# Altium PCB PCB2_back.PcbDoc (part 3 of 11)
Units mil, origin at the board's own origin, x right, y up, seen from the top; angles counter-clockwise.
Board outline 6299 x 3937 mil, 4 copper layers (TopLayer, GROUND, VCC, BottomLayer); 290 components, 470 nets, 2252 pads, 825 vias.
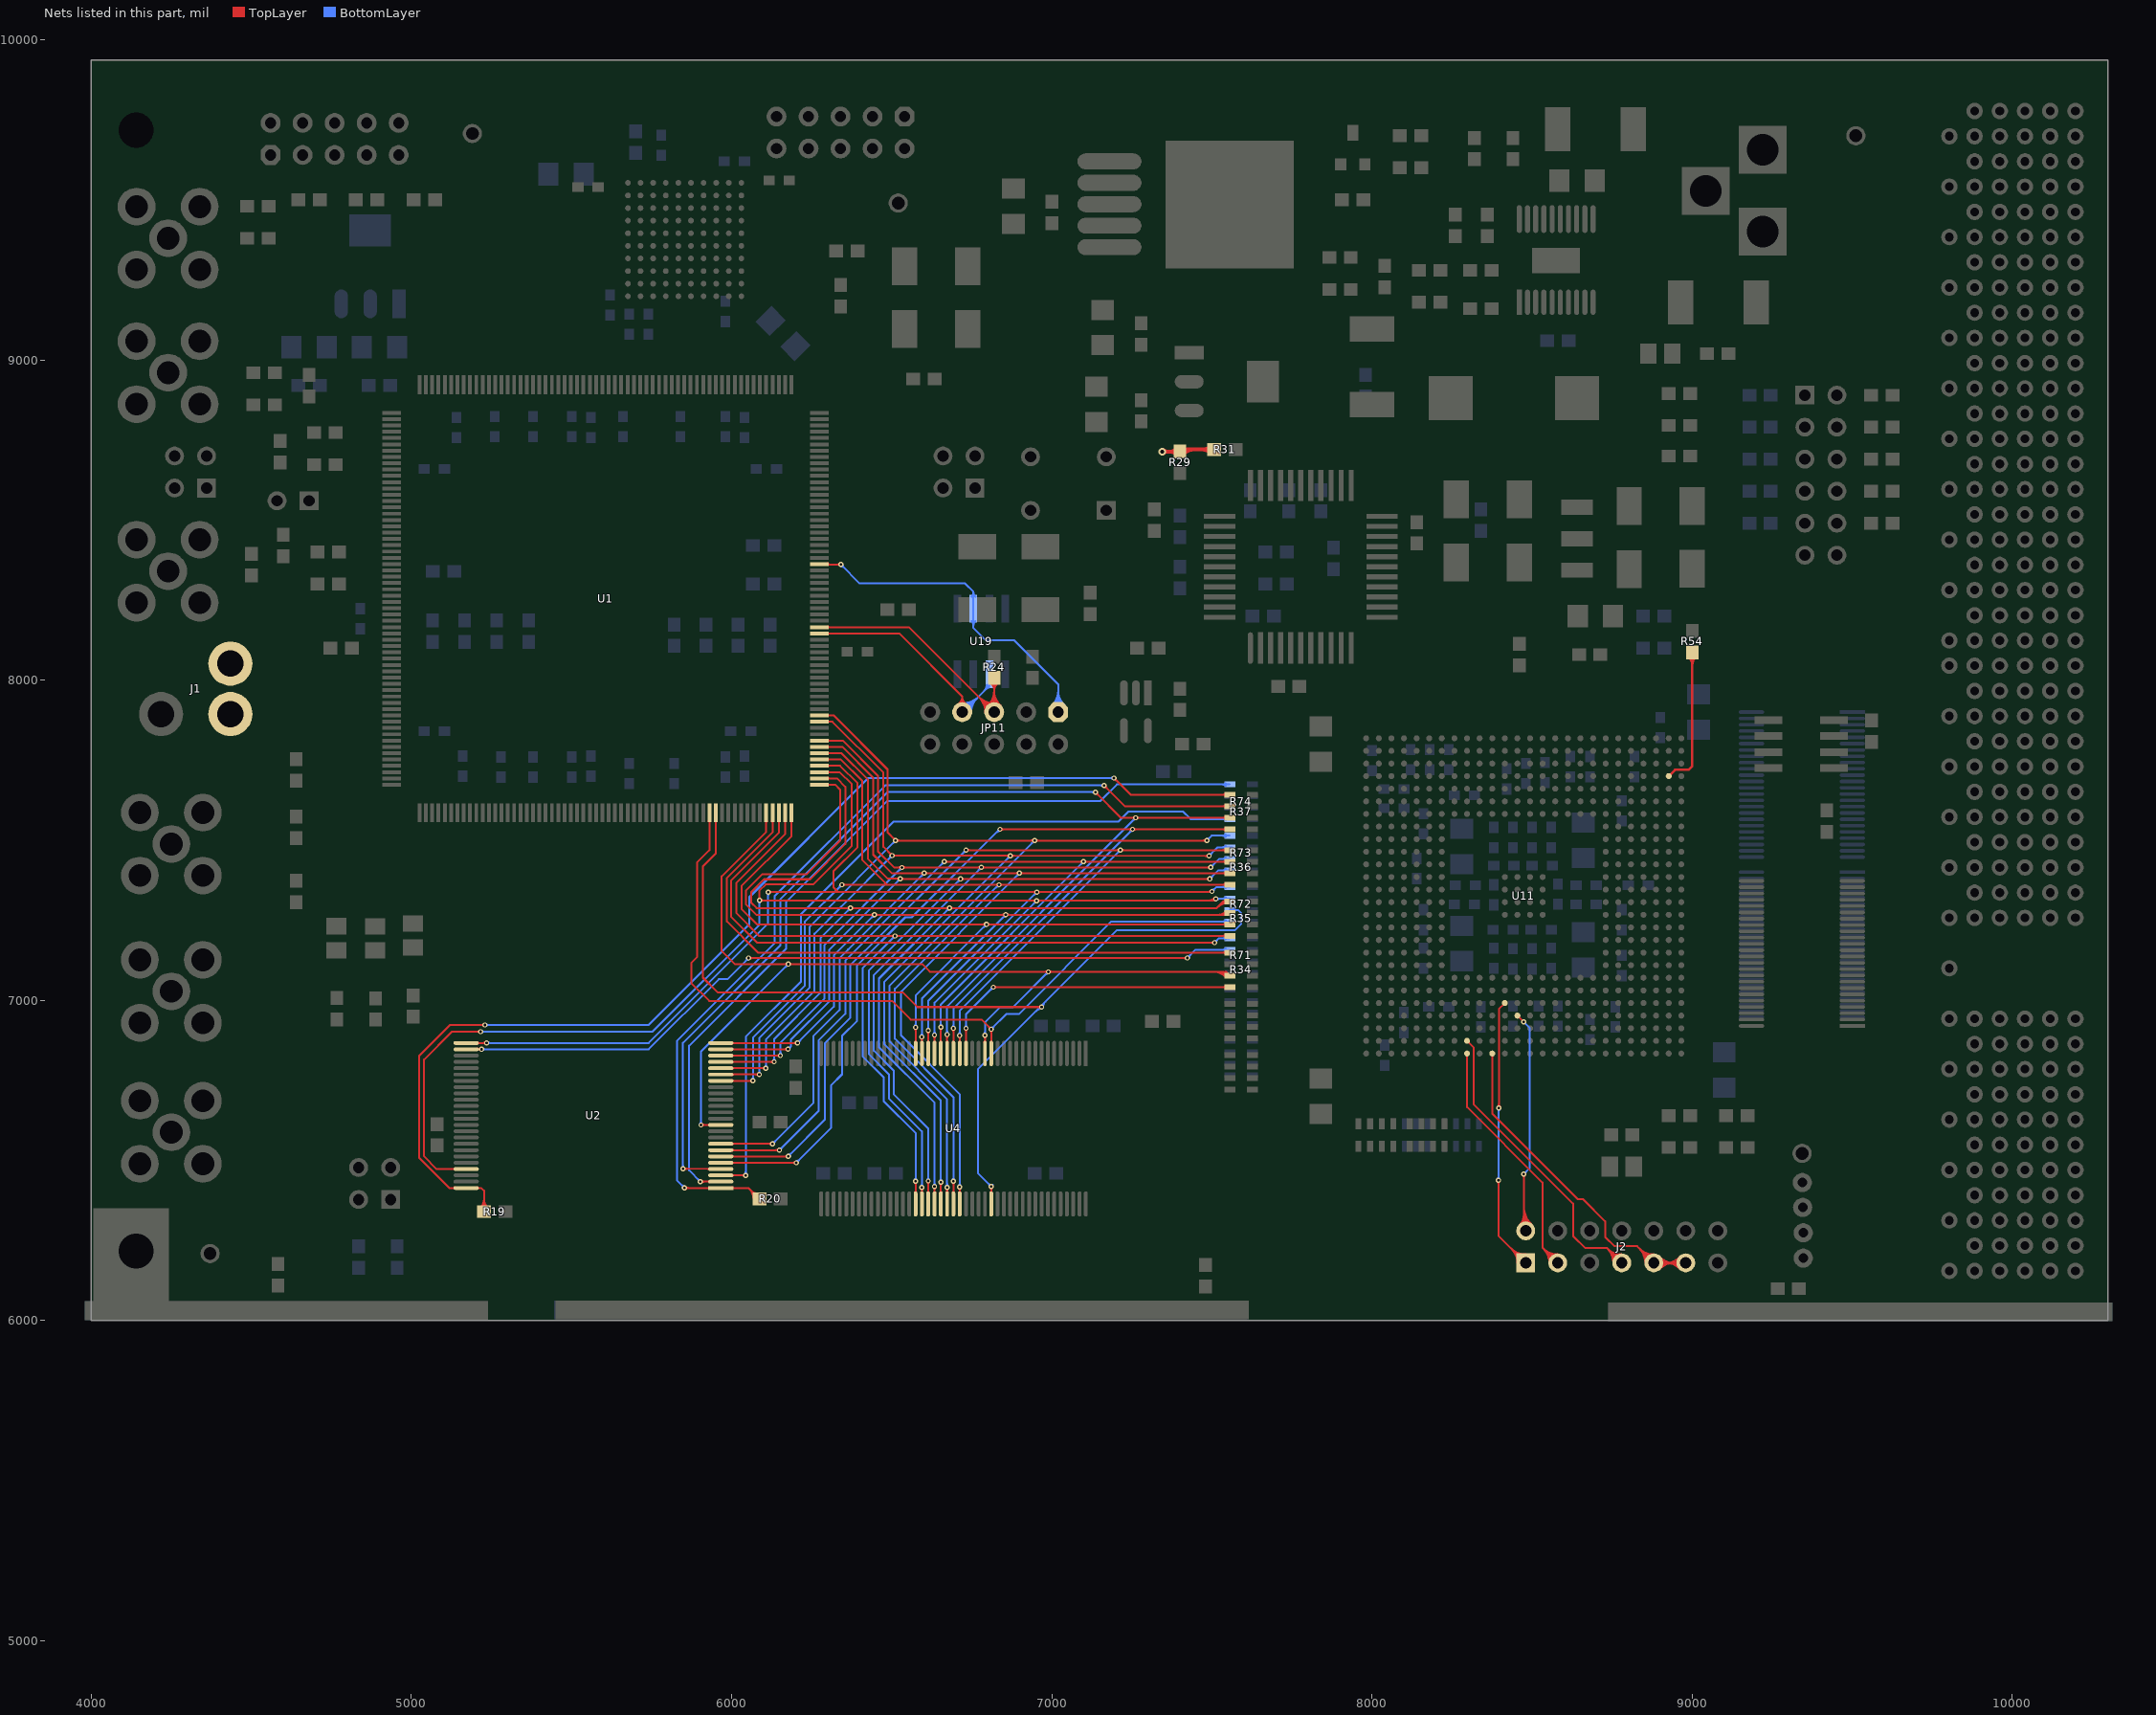
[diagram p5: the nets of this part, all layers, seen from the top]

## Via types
v1: diameter 16, hole 8, TopLayer to BottomLayer, 408 vias
v2: diameter 20, hole 10, TopLayer to BottomLayer, 221 vias
v3: diameter 24, hole 12, TopLayer to BottomLayer, 194 vias
v4: diameter 56.69, hole 56.69, TopLayer to BottomLayer, 2 vias

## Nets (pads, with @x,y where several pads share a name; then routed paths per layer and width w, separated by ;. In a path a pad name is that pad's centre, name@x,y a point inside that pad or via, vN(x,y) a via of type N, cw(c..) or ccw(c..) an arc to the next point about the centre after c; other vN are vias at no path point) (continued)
AS_DCLK: JP11.1 U1.36 U19.6 | length 1418.3
  TopLayer w6: U1.36@6274.31,8362.27 6275.57,8361 v1(6341,8361) ; U1.36@6299.98,8364.32 ccw(c6308,8372.34) 6308,8361 ; v1@6337.46,8357.46 ccw(c6328.93,8348.93) 6328.93,8361 ccw(c6328.93,8373.07) v1@6337.46,8364.54
  BottomLayer w6: v1@6341,8356 cw(c6341,8343.93) 6349.54,8352.46 cw(c6358.07,8361) v1@6346,8361 ; v1(6341,8361) 6400,8302 6729,8302 6755,8276 6755,8163 6794,8124 6883,8124 7020,7987 JP11.1@7020,7900 ; U19.6@6748.77,8184.64 cw(c6733.73,8169.59) 6755,8169.59 cw(c6776.27,8169.59) U19.6@6761.23,8184.64 ; U19.6@6748.77,8260.09 ccw(c6733.73,8275.13) 6755,8275.13 ccw(c6776.27,8275.13) U19.6@6761.23,8260.09 ; JP11.1@7000.2,7919.8 ccw(c6952.4,7967.6) 7020,7967.6 ccw(c7087.6,7967.6) JP11.1@7039.8,7919.8 ; JP11.1@7004.44,7915.56 ccw(c6966.89,7953.11) 7020,7953.11 ccw(c7073.11,7953.11) JP11.1@7035.56,7915.56 ; JP11.1@7008.69,7911.31 ccw(c6981.37,7938.63) 7020,7938.63 ccw(c7058.63,7938.63) JP11.1@7031.31,7911.31
AS_NCONFIG: JP11.5 R24.1 U1.26 | length 1377.6
  TopLayer w6: U1.26@6274.31,8165.42 6553.58,8165.42 6819,7900 JP11.5@6820,7900 R24.1@6820,8006.54 ; U1.26@6299.98,8163.36 cw(c6304.94,8158.4) 6304.94,8165.42 cw(c6304.94,8172.43) U1.26@6299.98,8167.47 ; 6770.49,7948.51 ccw(c6820,7998.01) JP11.5@6820,7928 ; 6772.91,7946.09 cw(c6726.82,7900) JP11.5@6792,7900 ; 6780.74,7938.26 ccw(c6820,7977.53) JP11.5@6820,7922 ; 6783.15,7935.85 cw(c6747.3,7900) JP11.5@6798,7900 ; 6790.98,7928.02 ccw(c6820,7957.04) JP11.5@6820,7916 ; 6793.39,7925.61 cw(c6767.79,7900) JP11.5@6804,7900 ; JP11.5@6800.2,7919.8 ccw(c6752.4,7967.6) 6820,7967.6 ccw(c6887.6,7967.6) JP11.5@6839.8,7919.8 ; JP11.5@6804.44,7915.56 ccw(c6766.89,7953.11) 6820,7953.11 ccw(c6873.11,7953.11) JP11.5@6835.56,7915.56 ; R24.1@6808.2,7992.77 cw(c6779.72,7964.29) 6820,7964.29 cw(c6860.28,7964.29) R24.1@6831.8,7992.77 ; JP11.5@6808.69,7911.31 ccw(c6781.37,7938.63) 6820,7938.63 ccw(c6858.63,7938.63) JP11.5@6831.31,7911.31 ; R24.1@6812.44,7997.01 cw(c6794.2,7978.77) 6820,7978.77 cw(c6845.8,7978.77) R24.1@6827.56,7997.01
AWE#: R34.7 U1.236 U2.11 U4.17 | length 3475.7
  TopLayer w6: v1(5904.15,6610.85) U2.11@5966,6610.85 ; v1@5907.69,6607.31 cw(c5916.22,6598.78) 5916.22,6610.85 cw(c5916.22,6622.92) v1@5907.69,6614.39 ; U2.11@5930.48,6608.8 ccw(c5925.52,6603.84) 5925.52,6610.85 ccw(c5925.52,6617.86) U2.11@5930.48,6612.9 ; U1.236@6105.91,7560.02 cw(c6100.95,7555.06) 6107.97,7555.06 cw(c6114.98,7555.06) U1.236@6110.02,7560.02 ; U1.236@6107.97,7585.69 6107.97,7525.97 5969,7387 5969,7154 6010,7113 6595,7113 6619,7089 7543.84,7089 R34.7@7555.84,7077 ; v1@6173.46,7109.46 ccw(c6164.93,7100.93) 6164.93,7113 ccw(c6164.93,7125.07) v1@6173.46,7116.54 ; v1@6180.54,7109.46 cw(c6189.07,7100.93) 6189.07,7113 cw(c6189.07,7125.07) v1@6180.54,7116.54 ; v1@6787.5,6887.5 cw(c6778.97,6878.97) 6791.04,6878.97 cw(c6803.11,6878.97) v1@6794.58,6887.5 ; U4.17@6788.99,6869.52 ccw(c6784.03,6874.48) 6791.04,6874.48 ccw(c6798.05,6874.48) U4.17@6793.09,6869.52 ; U4.17@6791.04,6834 v1(6791.04,6891.04) ; v1@6985.46,7085.46 ccw(c6976.93,7076.93) 6976.93,7089 ccw(c6976.93,7101.07) v1@6985.46,7092.54 ; v1@6992.54,7085.46 cw(c7001.07,7076.93) 7001.07,7089 cw(c7001.07,7101.07) v1@6992.54,7092.54 ; 7503.89,7089 cw(c7503.89,7033.54) R34.7@7543.1,7072.76 ; 7518.37,7089 cw(c7518.37,7048.03) 7547.34,7077 ccw(c7539.22,7080.89) 7545.59,7087.26 ; 7532.86,7089 cw(c7532.86,7062.51) R34.7@7551.59,7081.24
  BottomLayer w6: v1@5900.61,6614.39 ccw(c5892.08,6622.92) 5904.15,6622.92 ccw(c5916.22,6622.92) v1@5907.69,6614.39 ; v1(5904.15,6610.85) 5904.15,6840.15 v1(6177,7113) ; v1@6172,7113 cw(c6159.93,7113) 6168.46,7104.46 cw(c6177,7095.93) v1@6177,7108 ; v1@6787.5,6894.58 ccw(c6778.97,6903.11) 6791.04,6903.11 ccw(c6803.11,6903.11) v1@6794.58,6894.58 ; v1(6791.04,6891.04) 6791.04,6931.04 6838.94,6978.94 6878.94,6978.94 v1(6989,7089) ; v1@6984,7089 cw(c6971.93,7089) 6980.46,7080.46 cw(c6989,7071.93) v1@6989,7084
BE0#: R72.5 U1.227 U4.16 | length 2613.5
  TopLayer w6: U1.227@5928.75,7560.02 cw(c5923.79,7555.06) 5930.8,7555.06 cw(c5937.82,7555.06) U1.227@5932.86,7560.02 ; U1.227@5930.8,7585.69 5930.8,7468.8 5892,7430 5892,7135 5874,7117 5874,7054 5930,6998 6501,6998 6559,6940 6780.45,6940 v1(6810.73,6909.73) U4.16@6810.73,6834 ; v1@6805.73,6909.73 ccw(c6793.65,6909.73) 6802.19,6918.26 ccw(c6810.73,6926.8) v1@6810.73,6914.72 ; v1@6807.19,6906.19 cw(c6798.65,6897.65) 6810.73,6897.65 cw(c6822.8,6897.65) v1@6814.26,6906.19 ; U4.16@6808.67,6869.52 ccw(c6803.71,6874.48) 6810.73,6874.48 ccw(c6817.74,6874.48) U4.16@6812.78,6869.52
  BottomLayer w6: v1(6810.73,6909.73) 6859,6958 6898,6958 7186,7246 R72.5@7555.84,7246 ; v1@6810.73,6914.72 ccw(c6810.73,6926.8) 6819.26,6918.26 ccw(c6827.8,6909.73) v1@6815.72,6909.73 ; R72.5@7543.1,7241.76 ccw(c7532.86,7231.51) 7532.86,7246 ccw(c7532.86,7260.49) R72.5@7543.1,7250.24
BE1#: R72.6 U1.228 U4.71 | length 3295.6
  TopLayer w6: U1.228@5948.43,7560.02 cw(c5943.47,7555.06) 5950.49,7555.06 cw(c5957.5,7555.06) U1.228@5952.54,7560.02 ; U1.228@5950.49,7585.69 5950.49,7458.49 5910,7418 5910,7071 5956,7025 6534,7025 6580,6979 v1(6968,6979) ; v1@6807.19,6415.19 cw(c6798.65,6406.65) 6810.73,6406.65 cw(c6822.8,6406.65) v1@6814.26,6415.19 ; U4.71@6808.67,6399.52 ccw(c6803.71,6404.48) 6810.73,6404.48 ccw(c6817.74,6404.48) U4.71@6812.78,6399.52 ; U4.71@6810.73,6364 v1(6810.73,6418.73) ; v1@6964.46,6975.46 ccw(c6955.93,6966.93) 6955.93,6979 ccw(c6955.93,6991.07) v1@6964.46,6982.54
  BottomLayer w6: v1@6805.73,6418.73 ccw(c6793.65,6418.73) 6802.19,6427.26 ccw(c6810.73,6435.8) v1@6810.73,6423.72 ; v1@6816,6424 v1(6810.73,6418.73) 6770,6459.45 6770,6786 7203,7219 7572,7219 7591,7238 7591,7273 7582,7282 R72.6@7555.84,7282 ; 6950.93,6966.93 cw(c6968,6949.86) v1@6968,6974 ; v1@6973,6979 cw(c6997.14,6979) 6980.07,6996.07 ; R72.6@7568.59,7277.76 cw(c7578.83,7267.51) 7578.83,7282 cw(c7578.83,7296.49) R72.6@7568.59,7286.24
BE2#: R35.7 U1.240 U4.28 | length 2544.3
  TopLayer w6: U1.240@6184.65,7560.02 cw(c6179.69,7555.06) 6186.71,7555.06 cw(c6193.72,7555.06) U1.240@6188.76,7560.02 ; U1.240@6186.71,7585.69 6186.71,7512.71 6031,7357 6031,7285 6079,7237 R35.7@7555.84,7237 ; v1@6570.97,6911.97 cw(c6562.43,6903.43) 6574.51,6903.43 cw(c6586.58,6903.43) v1@6578.04,6911.97 ; U4.28@6572.45,6869.52 ccw(c6567.49,6874.48) 6574.51,6874.48 ccw(c6581.52,6874.48) U4.28@6576.56,6869.52 ; U4.28@6574.51,6834 v1(6574.51,6915.51) ; v1@6792.46,7233.46 ccw(c6783.93,7224.93) 6783.93,7237 ccw(c6783.93,7249.07) v1@6792.46,7240.54 ; v1@6799.54,7233.46 cw(c6808.07,7224.93) 6808.07,7237 cw(c6808.07,7249.07) v1@6799.54,7240.54 ; R35.7@7543.1,7232.76 ccw(c7532.86,7222.51) 7532.86,7237 ccw(c7532.86,7251.49) R35.7@7543.1,7241.24
  BottomLayer w6: v1@6570.97,6919.04 ccw(c6562.43,6927.58) 6574.51,6927.58 ccw(c6586.58,6927.58) v1@6578.04,6919.04 ; v1(6574.51,6915.51) 6574.51,7015.51 v1(6796,7237) ; v1@6791,7237 cw(c6778.93,7237) 6787.46,7228.46 cw(c6796,7219.93) v1@6796,7232
BE3#: R35.8 U1.239 U4.59 | length 3034.7
  TopLayer w6: U1.239@6164.97,7560.02 cw(c6160.01,7555.06) 6167.02,7555.06 cw(c6174.04,7555.06) U1.239@6169.08,7560.02 ; U1.239@6167.02,7585.69 6167.02,7519.02 6014,7366 6014,7273 6086,7201 R35.8@7555.84,7201 ; v1@6506.46,7197.46 ccw(c6497.93,7188.93) 6497.93,7201 ccw(c6497.93,7213.07) v1@6506.46,7204.54 ; v1@6513.54,7197.46 cw(c6522.07,7188.93) 6522.07,7201 cw(c6522.07,7213.07) v1@6513.54,7204.54 ; v1@6570.97,6431.97 cw(c6562.43,6423.43) 6574.51,6423.43 cw(c6586.58,6423.43) v1@6578.04,6431.97 ; U4.59@6572.45,6399.52 ccw(c6567.49,6404.48) 6574.51,6404.48 ccw(c6581.52,6404.48) U4.59@6576.56,6399.52 ; U4.59@6574.51,6364 v1(6574.51,6435.51) ; R35.8@7543.1,7196.76 ccw(c7532.86,7186.51) 7532.86,7201 ccw(c7532.86,7215.49) R35.8@7543.1,7205.24
  BottomLayer w6: v1@6505,7201 cw(c6492.93,7201) 6501.46,7192.46 cw(c6510,7183.93) v1@6510,7196 ; v1(6510,7201) 6409,7100 6409,6825 6475,6759 6475,6685 6574.51,6585.49 v1(6574.51,6435.51) ; v1@6570.97,6439.04 ccw(c6562.43,6447.58) 6574.51,6447.58 ccw(c6586.58,6447.58) v1@6578.04,6439.04
CE0#: R34.8 U4.20 | length 1090.7
  TopLayer w6: v1@6728.45,6908.78 cw(c6719.91,6900.24) 6731.98,6900.24 cw(c6744.06,6900.24) v1@6735.52,6908.78 ; U4.20@6729.93,6869.52 ccw(c6724.97,6874.48) 6731.99,6874.48 ccw(c6739,6874.48) U4.20@6734.04,6869.52 ; U4.20@6731.98,6834 v1(6731.98,6912.31) ; v1(6817,7041) R34.8@7555.84,7041 ; v1@6820.54,7037.46 cw(c6829.07,7028.93) 6829.07,7041 cw(c6829.07,7053.07) v1@6820.54,7044.54 ; R34.8@7543.1,7036.76 ccw(c7532.86,7026.51) 7532.86,7041 ccw(c7532.86,7055.49) R34.8@7543.1,7045.24
  BottomLayer w6: v1@6728.45,6915.85 ccw(c6719.91,6924.39) 6731.98,6924.39 ccw(c6744.06,6924.39) v1@6735.52,6915.85 ; v1(6731.98,6912.31) 6731.98,6955.98 v1(6817,7041) ; v1@6812,7041 cw(c6799.93,7041) 6808.46,7032.46 cw(c6817,7023.93) v1@6817,7036
CE1#: R71.7 U2.26 | length 2661.4
  TopLayer w6: U2.26@5170.72,6847.07 v1(5219,6847) ; U2.26@5206.24,6845.01 cw(c5211.08,6840.16) v1@5211.09,6847.01 ; U2.26@5206.25,6849.12 ccw(c5211.33,6854.19) v1@5211.32,6847.01 ; v1@5215.46,6843.47 ccw(c5206.91,6834.95) 5206.93,6847.02 ccw(c5206.95,6859.09) v1@5215.47,6850.54 ; v1(6053,7132) v1(7423,7132) ; v1@6056.54,7128.46 cw(c6065.07,7119.93) 6065.07,7132 cw(c6065.07,7144.07) v1@6056.54,7135.54 ; v1@7419.46,7128.46 ccw(c7410.93,7119.93) 7410.93,7132 ccw(c7410.93,7144.07) v1@7419.46,7135.54
  BottomLayer w6: v1(5219,6847) 5576.07,6847.07 5741.07,6847.07 5960,7066 5987,7066 v1(6053,7132) ; v1@5222.54,6843.47 cw(c5231.07,6834.93) 5231.07,6847 cw(c5231.07,6859.07) v1@5222.53,6850.54 ; v1@6048,7132 cw(c6035.93,7132) 6044.46,7123.46 cw(c6053,7114.93) v1@6053,7127 ; v1(7423,7132) 7449,7158 R71.7@7555.84,7158 ; v1@7423,7137 ccw(c7423,7149.07) 7431.54,7140.54 ccw(c7440.07,7132) v1@7428,7132 ; R71.7@7543.1,7153.76 ccw(c7532.86,7143.51) 7532.86,7158 ccw(c7532.86,7172.49) R71.7@7543.1,7162.24
CE2#: R71.8 U1.238 | length 2054.9
  TopLayer w6: U1.238@6145.28,7560.02 cw(c6140.32,7555.06) 6147.34,7555.06 cw(c6154.35,7555.06) U1.238@6149.39,7560.02 ; U1.238@6147.34,7585.69 6147.34,7523.34 5998,7374 5998,7262 6080,7180 v1(7508,7180) ; v1@7504.46,7176.46 ccw(c7495.93,7167.93) 7495.93,7180 ccw(c7495.93,7192.07) v1@7504.46,7183.54
  BottomLayer w6: v1(7508,7180) 7522,7194 R71.8@7555.84,7194 ; v1@7508,7185 ccw(c7508,7197.07) 7516.54,7188.54 ccw(c7525.07,7180) v1@7513,7180 ; R71.8@7543.1,7189.76 ccw(c7532.86,7179.51) 7532.86,7194 ccw(c7532.86,7208.49) R71.8@7543.1,7198.24
CE3#: R34.5 U1.237 | length 2043.6
  TopLayer w6: U1.237@6125.6,7560.02 cw(c6120.64,7555.06) 6127.65,7555.06 cw(c6134.67,7555.06) U1.237@6129.71,7560.02 ; U1.237@6127.65,7585.69 6127.65,7524.65 5985,7382 5985,7246 6082,7149 R34.5@7555.84,7149 ; R34.5@7543.1,7144.76 ccw(c7532.86,7134.51) 7532.86,7149 ccw(c7532.86,7163.49) R34.5@7543.1,7153.24
CVBS: J1.1 R29.2 R31.2 | length 343.2
  TopLayer w12: v3(7344.54,8713.46) R29.2@7400,8713.46 7406.54,8720 R31.2@7506.54,8720 ; v3@7348.78,8709.22 cw(c7359.02,8698.98) 7359.02,8713.46 cw(c7359.02,8727.95) v3@7348.78,8717.71 ; R29.2@7390.32,8703.79 ccw(c7366.96,8680.43) 7366.96,8713.46 ccw(c7366.96,8746.5) R29.2@7390.32,8723.14 ; R29.2@7409.68,8705.76 cw(c7444.06,8671.37) 7444.06,8720 ; R29.2@7409.68,8725.11 ccw(c7422.01,8737.45) 7422.01,8720 ; R31.2@7494.89,8710.32 ccw(c7471.53,8686.96) 7471.53,8720 ccw(c7471.53,8753.04) R31.2@7494.89,8729.68
DATA: JP11.7 U1.25 U19.2 | length 1145.8
  TopLayer w6: U1.25@6274.31,8145.73 6523.27,8145.73 6720,7949 ; U1.25@6299.98,8143.68 cw(c6304.94,8138.72) 6304.94,8145.73 cw(c6304.94,8152.75) U1.25@6299.98,8147.79 ; JP11.7@6705.79,7924.12 ccw(c6691.13,7949) 6720,7949 ; JP11.7@6708.83,7918.95 ccw(c6697.32,7938.5) 6720,7938.5 ccw(c6742.68,7938.5) JP11.7@6731.17,7918.95 ; JP11.7@6720,7900 6720,7949 ; JP11.7@6734.21,7924.12 cw(c6748.87,7949) 6720,7949
  BottomLayer w6: JP11.7@6720,7900 6723,7900 6805,7982 U19.2@6805,8017.64 ; JP11.7@6720,7916 ccw(c6720,7961.87) 6752.44,7929.44 ; JP11.7@6720,7922 ccw(c6720,7982.36) 6762.68,7939.68 ; JP11.7@6720,7928 ccw(c6720,8002.84) 6772.92,7949.92 ; JP11.7@6736,7900 cw(c6767.38,7900) 6745.19,7922.19 ; JP11.7@6742,7900 cw(c6787.87,7900) 6755.44,7932.44 ; JP11.7@6748,7900 cw(c6808.36,7900) 6765.68,7942.68 ; 6787.03,7964.03 ccw(c6764.92,7986.14) U19.2@6796.19,7986.14 ; 6797.03,7974.03 cw(c6805,7966.06) U19.2@6805,7977.33 ; 6797.27,7974.27 ccw(c6785.4,7986.14) U19.2@6802.19,7986.14
DSP_CLKIN: R54.2 U11.AC2 | length 501.2
  TopLayer w8: U11.AC2@8926.63,7700.14 8946.49,7720 8989,7720 9000,7731 R54.2@9000,8086.54 ; R54.2@8988.91,8073.48 cw(c8962.13,8046.7) 9000,8046.7 cw(c9037.87,8046.7) R54.2@9011.09,8073.48
DSP_T\R\S\T\: J2.2 U11.D14 | length 990
  TopLayer w6: U11.D14@8454.19,6952.11 v1(8474,6932.3) ; J2.2@8461.24,6298.76 ccw(c8430.44,6329.56) 8474,6329.56 ccw(c8529.56,6329.56) J2.2@8490.27,6290.27 ; J2.2@8465.48,6294.52 ccw(c8444.93,6315.07) 8474,6315.07 ccw(c8515.07,6315.07) J2.2@8486.03,6286.03 ; v1@8470.46,6453.46 cw(c8461.93,6444.93) 8474,6444.93 cw(c8486.07,6444.93) v1@8477.54,6453.46 ; 8474,6344.04 ccw(c8544.04,6344.04) J2.2@8494.52,6294.52 ; 8474,6358.53 ccw(c8558.53,6358.53) J2.2@8498.76,6298.76 ; v1(8474,6457) 8474,6286 J2.2@8480,6280
  BottomLayer w6: v1(8474,6457) 8492,6475 8492,6914.3 v1(8474,6932.3) ; v1@8474,6462 ccw(c8474,6474.07) 8482.54,6465.54 ccw(c8491.07,6457) v1@8479,6457
DSP_TCLK: J2.9 J2.11 U11.A16 | length 1714.6
  TopLayer w6: U11.A16@8375.45,6834 8375.45,6646.55 8643,6379 8659,6379 8728,6310 8728,6261 8757,6232 8828,6232 J2.9@8880,6180 J2.11@8980,6180 ; J2.9@8853.47,6180 ccw(c8789.43,6180) 8834.71,6225.29 ccw(c8880,6270.57) J2.9@8880,6206.53 ; J2.9@8859.47,6180 ccw(c8809.91,6180) 8844.96,6215.04 ccw(c8880,6250.09) J2.9@8880,6200.53 ; J2.9@8865.47,6180 ccw(c8830.4,6180) 8855.2,6204.8 ccw(c8880,6229.6) J2.9@8880,6194.53 ; J2.9@8890.27,6169.73 cw(c8915.07,6144.93) 8915.07,6180 cw(c8915.07,6215.07) J2.9@8890.27,6190.27 ; J2.9@8894.52,6165.48 cw(c8929.56,6130.44) 8929.56,6180 cw(c8929.56,6229.56) J2.9@8894.52,6194.52 ; J2.9@8898.76,6161.24 cw(c8944.04,6115.96) 8944.04,6180 cw(c8944.04,6244.04) J2.9@8898.76,6198.76 ; J2.11@8961.24,6161.24 ccw(c8915.96,6115.96) 8915.96,6180 ccw(c8915.96,6244.04) J2.11@8961.24,6198.76 ; J2.11@8965.48,6165.48 ccw(c8930.44,6130.44) 8930.44,6180 ccw(c8930.44,6229.56) J2.11@8965.48,6194.52 ; J2.11@8969.73,6169.73 ccw(c8944.93,6144.93) 8944.93,6180 ccw(c8944.93,6215.07) J2.11@8969.73,6190.27
DSP_TDI: J2.3 U11.A18 | length 1004.9
  TopLayer w6: U11.A18@8296.71,6834 8296.71,6666.29 8532,6431 8532,6228 J2.3@8580,6180 ; J2.3@8553.47,6180 ccw(c8489.43,6180) 8534.71,6225.29 ccw(c8580,6270.57) J2.3@8580,6206.53 ; J2.3@8559.47,6180 ccw(c8509.91,6180) 8544.96,6215.04 ccw(c8580,6250.09) J2.3@8580,6200.53 ; J2.3@8565.47,6180 ccw(c8530.4,6180) 8555.2,6204.8 ccw(c8580,6229.6) J2.3@8580,6194.53
DSP_TDO: J2.7 U11.B18 | length 1166.9
  TopLayer w6: U11.B18@8296.71,6873.37 8317,6853.08 8317,6676 8628,6365 8628,6264 8666,6226 8734,6226 J2.7@8780,6180 ; J2.7@8753.47,6180 ccw(c8689.43,6180) 8734.71,6225.29 ccw(c8780,6270.57) J2.7@8780,6206.53 ; J2.7@8759.47,6180 ccw(c8709.91,6180) 8744.96,6215.04 ccw(c8780,6250.09) J2.7@8780,6200.53 ; J2.7@8765.47,6180 ccw(c8730.4,6180) 8755.2,6204.8 ccw(c8780,6229.6) J2.7@8780,6194.53
DSP_TMS: J2.1 U11.E15 | length 1164.3
  TopLayer w6: v1@8391.46,6434.46 cw(c8382.93,6425.93) 8395,6425.93 cw(c8407.07,6425.93) v1@8398.54,6434.46 ; v1@8392.46,6667.54 ccw(c8383.93,6676.07) 8396,6676.07 ccw(c8408.07,6676.07) v1@8399.54,6667.54 ; v1(8395,6438) 8395,6265 J2.1@8480,6180 ; v1(8396,6664) 8396,6972.66 U11.E15@8414.82,6991.48 ; J2.1@8453.47,6180 ccw(c8389.43,6180) 8434.71,6225.29 ccw(c8480,6270.57) J2.1@8480,6206.53 ; J2.1@8459.47,6180 ccw(c8409.91,6180) 8444.96,6215.04 ccw(c8480,6250.09) J2.1@8480,6200.53 ; J2.1@8465.47,6180 ccw(c8430.4,6180) 8455.2,6204.8 ccw(c8480,6229.6) J2.1@8480,6194.53
  BottomLayer w6: v1@8391.46,6441.54 ccw(c8382.93,6450.07) 8395,6450.07 ccw(c8407.07,6450.07) v1@8398.54,6441.54 ; v1@8392.46,6660.46 cw(c8386.34,6654.34) 8395,6654.34 ; v1(8395,6438) 8395,6663 v1(8396,6664) ; 8395,6649.51 cw(c8410.49,6649.51) v1@8399.54,6660.46
EA03: R72.7 U1.3 U2.45 U4.25 | length 4826.3
  TopLayer w6: U2.45@5135.21,6471 ccw(c5130.25,6466.04) 5130.25,6473.06 ccw(c5130.25,6480.07) U2.45@5135.21,6475.11 ; U2.45@5170.72,6473.06 5078.94,6473.06 5039,6513 5039,6815 5126,6902 v1(5216,6902) ; v1@5212.46,6898.46 ccw(c5203.93,6889.93) 5203.93,6902 ccw(c5203.93,6914.07) v1@5212.46,6905.54 ; v1@6083.46,7315.54 ccw(c6074.93,7324.07) 6087,7324.07 ccw(c6099.07,7324.07) 6090.54,7315.54 ccw(c6101.49,7326.49) 6101.49,7311 ; v1(6087,7312) 6087,7343 6106,7362 6254,7362 6375,7483 6375,7675 6337.34,7712.66 U1.3@6274.31,7712.66 ; v1@6088,7311 7506,7311 ; v1@6090.54,7308.46 cw(c6096.66,7302.34) 6096.66,7311 ; U1.3@6299.98,7710.61 cw(c6304.94,7705.65) 6304.94,7712.66 cw(c6304.94,7719.68) U1.3@6299.98,7714.72 ; v1@6630.02,6888.02 cw(c6621.49,6879.49) 6633.56,6879.49 cw(c6645.63,6879.49) v1@6637.1,6888.02 ; U4.25@6631.51,6869.52 ccw(c6626.55,6874.48) 6633.56,6874.48 ccw(c6640.57,6874.48) U4.25@6635.61,6869.52 ; U4.25@6633.56,6834 v1(6633.56,6891.56) ; v1@6948.46,7307.46 ccw(c6939.93,7298.93) 6939.93,7311 ccw(c6939.93,7323.07) v1@6948.46,7314.54 ; v1@6955.54,7307.46 cw(c6964.07,7298.93) 6964.07,7311 cw(c6964.07,7323.07) v1@6955.54,7314.54 ; 7485.44,7311 ccw(c7485.44,7343.56) v1@7508.46,7320.54 ; 7499.93,7311 ccw(c7499.93,7329.07) v1@7512.71,7316.29 ; v1@7507.19,7315.62 cw(c7502.68,7314.32) 7506,7311 ; v1@7510.62,7312.19 ccw(c7509.32,7307.68) 7506,7311 ; v1(7512,7317) 7506,7311
  BottomLayer w6: v1(5216,6902) 5753,6902 6087,7236 v1(6087,7312) ; v1@5219.54,6898.46 cw(c5228.07,6889.93) 5228.07,6902 cw(c5228.07,6914.07) v1@5219.54,6905.54 ; v1@6083.46,7308.46 cw(c6074.93,7299.93) 6087,7299.93 cw(c6099.07,7299.93) v1@6090.54,7308.46 ; v1@6630.02,6895.1 ccw(c6621.49,6903.63) 6633.56,6903.63 ccw(c6645.63,6903.63) v1@6637.1,6895.1 ; v1(6633.56,6891.56) 6633.56,6992.56 v1(6952,7311) ; v1@6947,7311 cw(c6934.93,7311) 6943.46,7302.46 cw(c6952,7293.93) v1@6952,7306 ; v1(7512,7317) R72.7@7554.84,7317 ; v1@7515.54,7313.46 cw(c7524.07,7304.93) 7524.07,7317 cw(c7524.07,7329.07) v1@7515.54,7320.54 ; 7530.44,7317 ccw(c7530.44,7334.9) R72.7@7543.1,7322.24 ; 7535.27,7317 cw(c7535.27,7305.93) R72.7@7543.1,7313.76
EA04: R72.8 U1.4 U2.25 U4.26 | length 4067.6
  TopLayer w6: U2.25@5170.72,6866.76 v1(5234.76,6866.76) ; U2.25@5206.24,6864.7 cw(c5211.2,6859.74) 5211.2,6866.76 cw(c5211.2,6873.77) U2.25@5206.24,6868.81 ; v1@5231.22,6863.22 ccw(c5222.68,6854.68) 5222.68,6866.76 ccw(c5222.68,6878.83) v1@5231.22,6870.29 ; v1(6114,7338) 7498,7338 v1(7500,7340) ; v1@6117.54,7334.46 cw(c6126.07,7325.93) 6126.07,7338 cw(c6126.07,7350.07) v1@6117.54,7341.54 ; U1.4@6274.31,7732.35 6338.65,7732.35 6393,7678 6393,7478 6318,7403 6318,7353 6333,7338 ; U1.4@6299.98,7730.29 cw(c6304.94,7725.33) 6304.94,7732.35 cw(c6304.94,7739.36) U1.4@6299.98,7734.4 ; v1@6610.34,6901.78 cw(c6601.8,6893.24) 6613.88,6893.24 cw(c6625.95,6893.24) v1@6617.41,6901.78 ; U4.26@6611.82,6869.52 ccw(c6606.86,6874.48) 6613.88,6874.48 ccw(c6620.89,6874.48) U4.26@6615.93,6869.52 ; U4.26@6613.88,6834 v1(6613.88,6905.31) ; v1@6949.46,7334.46 ccw(c6940.93,7325.93) 6940.93,7338 ccw(c6940.93,7350.07) v1@6949.46,7341.54 ; v1@6956.54,7334.46 cw(c6965.07,7325.93) 6965.07,7338 cw(c6965.07,7350.07) v1@6956.54,7341.54 ; 7483.1,7338 ccw(c7483.1,7356.9) v1@7496.46,7343.54
  BottomLayer w6: v1(5234.76,6866.76) 5740.76,6866.76 6114,7240 v1(6114,7338) ; v1@5238.29,6863.22 cw(c5246.83,6854.68) 5246.83,6866.76 cw(c5246.83,6878.83) v1@5238.29,6870.29 ; v1@6110.46,7334.46 cw(c6101.93,7325.93) 6114,7325.93 cw(c6126.07,7325.93) v1@6117.54,7334.46 ; v1@6610.34,6908.85 ccw(c6601.8,6917.39) 6613.88,6917.39 ccw(c6625.95,6917.39) v1@6617.41,6908.85 ; v1(6613.88,6905.31) 6613.88,6998.88 v1(6953,7338) ; v1@6948,7338 cw(c6935.93,7338) 6944.46,7329.46 cw(c6953,7320.93) v1@6953,7333 ; v1(7500,7340) 7514,7354 R72.8@7555.84,7354 ; v1@7500,7345 ccw(c7500,7357.07) 7508.54,7348.54 ccw(c7517.07,7340) v1@7505,7340 ; R72.8@7543.1,7349.76 ccw(c7532.86,7339.51) 7532.86,7354 ccw(c7532.86,7368.49) R72.8@7543.1,7358.24
EA05: R35.6 U1.1 U2.24 U4.27 | length 3706.4
  TopLayer w6: U2.24@5966,6866.76 v1(6205.76,6866.76) ; U2.24@6001.52,6864.7 cw(c6006.48,6859.74) 6006.48,6866.76 cw(c6006.48,6873.77) U2.24@6001.52,6868.81 ; v1@6202.22,6863.22 ccw(c6193.68,6854.68) 6193.68,6866.76 ccw(c6193.68,6878.83) v1@6202.22,6870.29 ; U1.1@6274.31,7673.29 6323.71,7673.29 6339,7658 6339,7499 6233,7393 6095,7393 6045,7343 6045,7299 6077,7267 7549.84,7267 R35.6@7555.84,7273 ; U1.1@6299.98,7671.24 cw(c6304.94,7666.28) 6304.94,7673.29 cw(c6304.94,7680.31) U1.1@6299.98,7675.35 ; v1@6442.46,7263.46 ccw(c6433.93,7254.93) 6433.93,7267 ccw(c6433.93,7279.07) v1@6442.46,7270.54 ; v1@6449.54,7263.46 cw(c6458.07,7254.93) 6458.07,7267 cw(c6458.07,7279.07) v1@6449.54,7270.54 ; v1@6590.65,6882.09 cw(c6582.12,6873.56) 6594.19,6873.56 cw(c6606.26,6873.56) v1@6597.73,6882.09 ; U4.27@6592.14,6869.52 ccw(c6587.18,6874.48) 6594.19,6874.48 ccw(c6601.2,6874.48) U4.27@6596.24,6869.52 ; U4.27@6594.19,6834 v1(6594.19,6885.63) ; v1@6852.46,7263.46 ccw(c6843.93,7254.93) 6843.93,7267 ccw(c6843.93,7279.07) v1@6852.46,7270.54 ; v1@6859.54,7263.46 cw(c6868.07,7254.93) 6868.07,7267 cw(c6868.07,7279.07) v1@6859.54,7270.54 ; 7518.37,7267 ccw(c7518.37,7301.97) R35.6@7543.1,7277.24 ; 7532.86,7267 ccw(c7532.86,7287.49) R35.6@7547.34,7273
  BottomLayer w6: v1(6205.76,6866.76) 6319,6980 6319,7140 v1(6446,7267) ; v1@6205.76,6871.76 ccw(c6205.76,6883.83) 6214.29,6875.29 ccw(c6222.83,6866.76) v1@6210.76,6866.76 ; v1@6441,7267 cw(c6428.93,7267) 6437.46,7258.46 cw(c6446,7249.93) v1@6446,7262 ; v1@6590.65,6889.17 ccw(c6582.12,6897.7) 6594.19,6897.7 ccw(c6606.26,6897.7) v1@6597.73,6889.17 ; v1(6594.19,6885.63) 6594.19,7005.19 v1(6856,7267) ; v1@6851,7267 cw(c6838.93,7267) 6847.46,7258.46 cw(c6856,7249.93) v1@6856,7262
EA06: R73.5 U1.6 U2.23 U4.60 | length 3974.6
  TopLayer w6: U2.23@5966,6847.07 v1(6176.07,6847.07) ; U2.23@6001.52,6845.02 cw(c6006.48,6840.06) 6006.48,6847.07 cw(c6006.48,6854.08) U2.23@6001.52,6849.12 ; v1@6172.53,6843.53 ccw(c6164,6835) 6164,6847.07 ccw(c6164,6859.14) v1@6172.53,6850.61 ; U1.6@6274.31,7771.72 6343.28,7771.72 6425,7690 6425,7442 6487.1,7379.9 v1(6526.9,7379.9) ; U1.6@6299.98,7769.66 cw(c6304.94,7764.7) 6304.94,7771.72 cw(c6304.94,7778.73) U1.6@6299.98,7773.77 ; v1@6523.37,7376.37 ccw(c6514.83,7367.83) 6514.83,7379.9 ccw(c6514.83,7391.98) v1@6523.37,7383.44 ; v1@6526.9,7379 v1(7493,7379) ; v1@6530.44,7376.37 cw(c6536.79,7370.02) 6536.79,7379 ; v1@6530.44,7383.44 ccw(c6541.16,7394.16) 6541.16,7379 ; v1@6590.65,6411.65 cw(c6582.12,6403.12) 6594.19,6403.12 cw(c6606.26,6403.12) v1@6597.73,6411.65 ; U4.60@6592.14,6399.52 ccw(c6587.18,6404.48) 6594.19,6404.48 ccw(c6601.2,6404.48) U4.60@6596.24,6399.52 ; U4.60@6594.19,6364 v1(6594.19,6415.19) ; v1@6711.46,7375.46 ccw(c6702.93,7366.93) 6702.93,7379 ccw(c6702.93,7391.07) v1@6711.46,7382.54 ; v1@6718.54,7375.46 cw(c6727.07,7366.93) 6727.07,7379 cw(c6727.07,7391.07) v1@6718.54,7382.54 ; v1@7489.46,7375.46 ccw(c7480.93,7366.93) 7480.93,7379 ccw(c7480.93,7391.07) v1@7489.46,7382.54
  BottomLayer w6: v1(6176.07,6847.07) 6185,6856 6185,6877 6305,6997 6305,7158 v1(6526.9,7379.9) ; v1@6176.07,6852.07 ccw(c6176.07,6864.14) 6184.61,6855.61 ccw(c6193.14,6847.07) v1@6181.07,6847.07 ; v1@6521.9,7379.9 cw(c6509.83,7379.9) 6518.37,7371.37 cw(c6526.9,7362.83) v1@6526.9,7374.9 ; v1@6590.65,6418.73 ccw(c6582.12,6427.26) 6594.19,6427.26 ccw(c6606.26,6427.26) v1@6597.73,6418.73 ; v1(6594.19,6415.19) 6594.19,6591 6491,6694.19 6491,6769 6428,6832 6428,7092 v1(6715,7379) ; v1@6710,7379 cw(c6697.93,7379) 6706.46,7370.46 cw(c6715,7361.93) v1@6715,7374 ; v1(7493,7379) 7520,7406 R73.5@7555.84,7406 ; v1@7493,7384 ccw(c7493,7396.07) 7501.54,7387.54 ccw(c7510.07,7379) v1@7498,7379 ; R73.5@7543.1,7401.76 ccw(c7532.86,7391.51) 7532.86,7406 ccw(c7532.86,7420.49) R73.5@7543.1,7410.24
EA07: R73.6 U1.8 U2.22 U4.61 | length 4070
  TopLayer w6: U2.22@5966,6827.39 v1(6152.39,6827.39) ; U2.22@6001.52,6825.33 cw(c6006.48,6820.37) 6006.48,6827.39 cw(c6006.48,6834.4) U2.22@6001.52,6829.44 ; v1@6148.85,6823.85 ccw(c6140.31,6815.31) 6140.31,6827.39 ccw(c6140.31,6839.46) v1@6148.85,6830.92 ; U1.8@6274.31,7811.09 6346.91,7811.09 6457,7701 6457,7465 6507.19,7414.81 v1(6531.81,7414.81) ; U1.8@6299.98,7809.03 cw(c6304.94,7804.07) 6304.94,7811.09 cw(c6304.94,7818.1) U1.8@6299.98,7813.14 ; v1@6528.28,7411.28 ccw(c6519.74,7402.74) 6519.74,7414.81 ccw(c6519.74,7426.89) v1@6528.28,7418.35 ; v1@6531.81,7415 v1(7496,7415) ; v1@6535.35,7411.28 cw(c6544.33,7402.3) 6544.33,7415 ; v1@6535.35,7418.35 ccw(c6543.44,7426.44) 6543.44,7415 ; v1@6610.34,6432.34 cw(c6601.8,6423.8) 6613.88,6423.8 cw(c6625.95,6423.8) v1@6617.41,6432.34 ; U4.61@6611.82,6399.52 ccw(c6606.86,6404.48) 6613.88,6404.48 ccw(c6620.89,6404.48) U4.61@6615.93,6399.52 ; U4.61@6613.88,6364 v1(6613.88,6435.88) ; v1@6776.46,7411.46 ccw(c6767.93,7402.93) 6767.93,7415 ccw(c6767.93,7427.07) v1@6776.46,7418.54 ; v1@6783.54,7411.46 cw(c6792.07,7402.93) 6792.07,7415 cw(c6792.07,7427.07) v1@6783.54,7418.54 ; v1@7492.46,7411.46 ccw(c7483.93,7402.93) 7483.93,7415 ccw(c7483.93,7427.07) v1@7492.46,7418.54
  BottomLayer w6: v1@6148.85,6830.92 ccw(c6140.31,6839.46) 6152.39,6839.46 ccw(c6164.46,6839.46) v1@6155.92,6830.92 ; v1(6152.39,6827.39) 6152.39,6868.39 6290,7006 6290,7173 v1(6531.81,7414.81) ; v1@6526.81,7414.81 cw(c6514.74,7414.81) 6523.28,7406.28 cw(c6531.81,7397.74) v1@6531.81,7409.81 ; v1@6610.34,6439.41 ccw(c6601.8,6447.95) 6613.88,6447.95 ccw(c6625.95,6447.95) v1@6617.41,6439.41 ; v1(6613.88,6435.88) 6613.88,6599 6506,6706.88 6506,6781 6444,6843 6444,7079 v1(6780,7415) ; v1@6775,7415 cw(c6762.93,7415) 6771.46,7406.46 cw(c6780,7397.93) v1@6780,7410 ; v1(7496,7415) 7523,7442 R73.6@7555.84,7442 ; v1@7496,7420 ccw(c7496,7432.07) 7504.54,7423.54 ccw(c7513.07,7415) v1@7501,7415 ; R73.6@7543.1,7437.76 ccw(c7532.86,7427.51) 7532.86,7442 ccw(c7532.86,7456.49) R73.6@7543.1,7446.24
EA08: R35.5 U1.2 U2.21 U4.62 | length 4322.9
  TopLayer w6: U2.21@5966,6807.7 v1(6132.7,6807.7) ; U2.21@6001.52,6805.65 cw(c6006.48,6800.69) 6006.48,6807.7 cw(c6006.48,6814.71) U2.21@6001.52,6809.75 ; v1@6129.16,6804.16 ccw(c6120.63,6795.63) 6120.63,6807.7 ccw(c6120.63,6819.77) v1@6129.16,6811.24 ; U1.2@6274.31,7692.98 6329.02,7692.98 6355,7667 6355,7488 6245,7378 6101,7378 6061,7338 6061,7305 6078,7288 7515,7288 7536,7309 ; U1.2@6299.98,7690.92 cw(c6304.94,7685.96) 6304.94,7692.98 cw(c6304.94,7699.99) U1.2@6299.98,7695.03 ; v1@6367.46,7284.46 ccw(c6358.93,7275.93) 6358.93,7288 ccw(c6358.93,7300.07) v1@6367.46,7291.54 ; v1@6374.54,7284.46 cw(c6383.07,7275.93) 6383.07,7288 cw(c6383.07,7300.07) v1@6374.54,7291.54 ; v1@6630.02,6415.02 cw(c6621.49,6406.49) 6633.56,6406.49 cw(c6645.63,6406.49) v1@6637.1,6415.02 ; U4.62@6631.51,6399.52 ccw(c6626.55,6404.48) 6633.56,6404.48 ccw(c6640.57,6404.48) U4.62@6635.61,6399.52 ; U4.62@6633.56,6364 v1(6633.56,6418.56) ; v1@6676.46,7284.46 ccw(c6667.93,7275.93) 6667.93,7288 ccw(c6667.93,7300.07) v1@6676.46,7291.54 ; v1@6683.54,7284.46 cw(c6692.07,7275.93) 6692.07,7288 cw(c6692.07,7300.07) v1@6683.54,7291.54 ; 7517.74,7290.74 cw(c7547.34,7261.13) R35.5@7547.34,7303 ; 7527.98,7300.98 cw(c7547.34,7281.62) 7547.34,7309 ccw(c7541.73,7301.64) 7535.18,7308.18 ; 7530.33,7303.33 cw(c7537.53,7296.13) R35.5@7543.71,7304.23 ; R35.5@7542.38,7305.62 ccw(c7536,7301.28) 7536,7309 ; R35.5@7542.38,7312.38 cw(c7536,7316.72) 7536,7309 ; R35.5@7555.84,7309 7536,7309
  BottomLayer w6: v1@6129.16,6811.24 ccw(c6120.63,6819.77) 6132.7,6819.77 ccw(c6144.77,6819.77) v1@6136.24,6811.24 ; v1(6132.7,6807.7) 6132.7,6879 6277,7023.3 6277,7194 v1(6371,7288) ; v1@6366,7288 cw(c6353.93,7288) 6362.46,7279.46 cw(c6371,7270.93) v1@6371,7283 ; v1@6630.02,6422.1 ccw(c6621.49,6430.63) 6633.56,6430.63 ccw(c6645.63,6430.63) v1@6637.1,6422.1 ; v1(6633.56,6418.56) 6633.56,6680.44 6460,6854 6460,7068 v1(6680,7288) ; v1@6675,7288 cw(c6662.93,7288) 6671.46,7279.46 cw(c6680,7270.93) v1@6680,7283
EA09: R73.7 U1.11 U2.20 U4.63 | length 4184.7
  TopLayer w6: U2.20@5966,6788.02 v1(6107.02,6788.02) ; U2.20@6001.52,6785.96 cw(c6006.48,6781) 6006.48,6788.02 cw(c6006.48,6795.03) U2.20@6001.52,6790.07 ; v1@6103.48,6784.48 ccw(c6094.94,6775.94) 6094.94,6788.02 ccw(c6094.94,6800.09) v1@6103.48,6791.55 ; U1.11@6274.31,7870.14 6314.86,7870.14 6474,7711 6474,7479 v1(6501,7452) 6870,7451.63 v1(7491,7451) ; U1.11@6299.98,7868.09 cw(c6304.94,7863.13) 6304.94,7870.14 cw(c6304.94,7877.16) U1.11@6299.98,7872.2 ; v1@6496,7452 ccw(c6483.93,7452) 6492.46,7460.54 ccw(c6501,7469.07) v1@6501,7457 ; v1@6504.53,7448.46 cw(c6513.06,7439.92) 6513.07,7451.99 cw(c6513.08,7464.06) v1@6504.54,7455.53 ; v1@6649.71,6428.22 cw(c6641.17,6419.68) 6653.24,6419.68 cw(c6665.32,6419.68) v1@6656.78,6428.22 ; U4.63@6651.19,6399.52 ccw(c6646.23,6404.48) 6653.24,6404.48 ccw(c6660.26,6404.48) U4.63@6655.3,6399.52 ; U4.63@6653.24,6364 v1(6653.24,6431.76) ; 6856.42,7451.64 cw(c6856.4,7437.43) v1@6866.46,7447.47 ; 6859.44,7451.64 ccw(c6859.45,7461.57) v1@6866.47,7454.54 ; v1@6873.53,7447.46 cw(c6883.57,7437.4) 6883.59,7451.61 ; v1@6873.54,7454.53 ccw(c6880.57,7461.55) 6880.56,7451.62 ; v1@7487.46,7447.47 ccw(c7478.92,7438.94) 7478.93,7451.01 ccw(c7478.94,7463.08) v1@7487.47,7454.54
  BottomLayer w6: v1@6103.48,6791.55 ccw(c6094.94,6800.09) 6107.02,6800.09 ccw(c6119.09,6800.09) v1@6110.55,6791.55 ; v1(6107.02,6788.02) 6107.02,6878.02 6259,7030 6259,7208 6342,7291 ; 6341.2,7291.8 v1(6501,7452) ; v1@6496,7451.99 cw(c6483.93,7451.98) 6492.48,7443.45 cw(c6501.02,7434.93) v1@6501.01,7447 ; v1@6649.71,6435.29 ccw(c6641.17,6443.83) 6653.24,6443.83 ccw(c6665.32,6443.83) v1@6656.78,6435.29 ; v1(6653.24,6431.76) 6653.24,6686.76 6477,6863 6477,7058 v1(6870,7451) ; v1@6865,7451 cw(c6852.93,7451) 6861.46,7442.46 cw(c6870,7433.93) v1@6870,7446 ; v1(7491,7451) 7518,7478 R73.7@7565,7478 ; v1@7491,7456 ccw(c7491,7468.07) 7499.54,7459.54 ccw(c7508.07,7451) v1@7496,7451 ; R73.7@7543.1,7473.76 ccw(c7532.86,7463.51) 7532.86,7478 ccw(c7532.86,7492.49) R73.7@7543.1,7482.24
EA10: R73.8 U1.12 U2.19 U4.64 | length 4272.6
  TopLayer w6: U2.19@5966,6768.33 v1(6086.33,6768.33) ; U2.19@6001.52,6766.28 cw(c6006.48,6761.32) 6006.48,6768.33 cw(c6006.48,6775.34) U2.19@6001.52,6770.38 ; v1@6082.79,6764.79 ccw(c6074.26,6756.26) 6074.26,6768.33 ccw(c6074.26,6780.4) v1@6082.79,6771.87 ; U1.12@6274.31,7889.83 6318.17,7889.83 6487,7721 6487,7524 v1(6512,7499) v1(7484,7499) ; U1.12@6299.98,7887.77 cw(c6304.94,7882.81) 6304.94,7889.83 cw(c6304.94,7896.84) U1.12@6299.98,7891.88 ; v1@6507,7499 ccw(c6494.93,7499) 6503.46,7507.54 ccw(c6512,7516.07) v1@6512,7504 ; v1@6515.54,7495.46 cw(c6524.07,7486.93) 6524.07,7499 cw(c6524.07,7511.07) v1@6515.54,7502.54 ; v1@6669.39,6412.53 cw(c6660.86,6404) 6672.93,6404 cw(c6685,6404) v1@6676.47,6412.53 ; U4.64@6670.88,6399.52 ccw(c6665.92,6404.48) 6672.93,6404.48 ccw(c6679.94,6404.48) U4.64@6674.98,6399.52 ; U4.64@6672.93,6364 v1(6672.93,6416.07) ; v1@6942.46,7495.46 ccw(c6933.93,7486.93) 6933.93,7499 ccw(c6933.93,7511.07) v1@6942.46,7502.54 ; v1@6949.54,7495.46 cw(c6958.07,7486.93) 6958.07,7499 cw(c6958.07,7511.07) v1@6949.54,7502.54 ; v1@7480.46,7495.46 ccw(c7471.93,7486.93) 7471.93,7499 ccw(c7471.93,7511.07) v1@7480.46,7502.54
  BottomLayer w6: v1@6082.79,6771.87 ccw(c6074.26,6780.4) 6086.33,6780.4 ccw(c6098.4,6780.4) v1@6089.87,6771.87 ; v1(6086.33,6768.33) 6086.33,6882 6244,7039.67 6244,7230 6271,7257 ; 6270.78,7257.22 v1(6512,7499) ; v1@6507,7498.99 cw(c6494.93,7498.98) 6503.47,7490.45 cw(c6512.02,7481.93) v1@6512.01,7494 ; v1@6669.39,6419.61 ccw(c6660.86,6428.14) 6672.93,6428.14 ccw(c6685,6428.14) v1@6676.47,6419.61 ; v1(6672.93,6416.07) 6672.93,6691.07 6493,6871 6493,7046 v1(6946,7499) ; v1@6941,7499 cw(c6928.93,7499) 6937.46,7490.46 cw(c6946,7481.93) v1@6946,7494 ; v1(7484,7499) 7499,7514 R73.8@7555.84,7514 ; v1@7484,7504 ccw(c7484,7516.07) 7492.54,7507.54 ccw(c7501.07,7499) v1@7489,7499 ; R73.8@7543.1,7509.76 ccw(c7532.86,7499.51) 7532.86,7514 ccw(c7532.86,7528.49) R73.8@7543.1,7518.24
EA11: R36.8 U1.5 U2.18 U4.65 | length 4027.7
  TopLayer w6: U2.18@5966,6748.65 v1(6066.65,6748.65) ; U2.18@6001.52,6746.59 cw(c6006.48,6741.63) 6006.48,6748.65 cw(c6006.48,6755.66) U2.18@6001.52,6750.7 ; v1@6063.11,6745.11 ccw(c6054.57,6736.57) 6054.57,6748.65 ccw(c6054.57,6760.72) v1@6063.11,6752.18 ; U1.5@6274.31,7752.03 6340.97,7752.03 6408,7685 6408,7438 6485,7361 6522,7361 ; U1.5@6299.98,7749.98 cw(c6304.94,7745.02) 6304.94,7752.03 cw(c6304.94,7759.05) U1.5@6299.98,7754.09 ; v1(6343.82,7360.82) 6522,7360.85 6835,7360.9 R36.8@7555.84,7361 ; v1@6347.36,7357.29 cw(c6355.9,7348.76) 6355.9,7360.83 cw(c6355.89,7372.9) v1@6347.36,7364.36 ; v1@6689.08,6431.85 cw(c6680.54,6423.31) 6692.61,6423.31 cw(c6704.69,6423.31) v1@6696.15,6431.85 ; U4.65@6690.56,6399.52 ccw(c6685.6,6404.48) 6692.61,6404.48 ccw(c6699.63,6404.48) U4.65@6694.67,6399.52 ; U4.65@6692.61,6364 v1(6692.61,6435.39) ; 6822.68,7360.89 ccw(c6822.68,7373.32) v1@6831.46,7364.54 ; 6823.18,7360.89 cw(c6823.18,7349.18) v1@6831.46,7357.46 ; v1@6838.54,7357.46 cw(c6846.82,7349.18) 6846.82,7360.9 ; v1@6838.54,7364.54 ccw(c6847.32,7373.32) 6847.32,7360.9 ; R36.8@7543.1,7356.76 ccw(c7532.86,7346.52) 7532.86,7361 ccw(c7532.85,7375.49) R36.8@7543.1,7365.24
  BottomLayer w6: v1@6063.11,6752.18 ccw(c6054.57,6760.72) 6066.65,6760.72 ccw(c6078.72,6760.72) v1@6070.18,6752.18 ; v1(6066.65,6748.65) 6066.65,6883.65 6229,7046 6229,7246 v1(6343.82,7360.82) ; v1@6338.82,7360.82 cw(c6326.75,7360.82) 6335.29,7352.29 cw(c6343.82,7343.75) v1@6343.82,7355.82 ; v1@6689.08,6438.92 ccw(c6680.54,6447.46) 6692.61,6447.46 ccw(c6704.69,6447.46) v1@6696.15,6438.92 ; v1(6692.61,6435.39) 6692.61,6697.39 6510,6880 6510,7036 v1(6835,7361) ; v1@6830,7361 cw(c6817.93,7361) 6826.46,7352.46 cw(c6835,7343.93) v1@6835,7356
EA12: R36.7 U1.7 U2.8 U4.66 | length 4295.5
  TopLayer w6: U2.8@5966,6551.8 v1(6127.8,6551.8) ; U2.8@6001.52,6549.74 cw(c6006.48,6544.78) 6006.48,6551.8 cw(c6006.48,6558.81) U2.8@6001.52,6553.85 ; v1@6124.26,6548.26 ccw(c6115.72,6539.72) 6115.72,6551.8 ccw(c6115.72,6563.87) v1@6124.26,6555.33 ; U1.7@6274.31,7791.4 6345.6,7791.4 6442,7695 6442,7455 6500,7397 R36.7@7555.84,7397 ; U1.7@6299.98,7789.35 cw(c6304.94,7784.39) 6304.94,7791.4 cw(c6304.94,7798.42) U1.7@6299.98,7793.46 ; v1@6597.46,7393.46 ccw(c6588.93,7384.93) 6588.93,7397 ccw(c6588.93,7409.07) v1@6597.46,7400.54 ; v1@6604.54,7393.46 cw(c6613.07,7384.93) 6613.07,7397 cw(c6613.07,7409.07) v1@6604.54,7400.54 ; v1@6708.76,6413.16 cw(c6700.23,6404.63) 6712.3,6404.63 cw(c6724.37,6404.63) v1@6715.84,6413.16 ; U4.66@6710.25,6399.52 ccw(c6705.29,6404.48) 6712.3,6404.48 ccw(c6719.31,6404.48) U4.66@6714.35,6399.52 ; U4.66@6712.3,6364 v1(6712.3,6416.7) ; v1@6895.46,7393.46 ccw(c6886.93,7384.93) 6886.93,7397 ccw(c6886.93,7409.07) v1@6895.46,7400.54 ; v1@6902.54,7393.46 cw(c6911.07,7384.93) 6911.07,7397 cw(c6911.07,7409.07) v1@6902.54,7400.54 ; R36.7@7543.1,7392.76 ccw(c7532.86,7382.51) 7532.86,7397 ccw(c7532.86,7411.49) R36.7@7543.1,7401.24
  BottomLayer w6: v1(6127.8,6551.8) 6255,6679 6255,6888 6337,6970 6337,7131 6364,7158 ; v1@6127.8,6556.8 ccw(c6127.8,6568.87) 6136.33,6560.33 ccw(c6144.87,6551.8) v1@6132.8,6551.8 ; 6363.31,7158.68 v1(6601,7397) ; v1@6596,7396.99 cw(c6583.93,7396.98) 6592.48,7388.45 cw(c6601.02,7379.93) v1@6601.01,7392 ; v1@6708.76,6420.24 ccw(c6700.23,6428.77) 6712.3,6428.77 ccw(c6724.37,6428.77) v1@6715.84,6420.24 ; v1(6712.3,6416.7) 6712.3,6706.7 6529,6890 6529,7027 v1(6899,7397) ; v1@6894,7397 cw(c6881.93,7397) 6890.46,7388.46 cw(c6899,7379.93) v1@6899,7392
EA13: R36.6 U2.7 U4.24 | length 3188.2
  TopLayer w6: U2.7@5966,6532.11 v1(6149.11,6532.11) ; U2.7@6001.52,6530.06 cw(c6006.48,6525.1) 6006.48,6532.11 cw(c6006.48,6539.12) U2.7@6001.52,6534.16 ; v1@6145.57,6528.57 ccw(c6137.04,6520.04) 6137.04,6532.11 ccw(c6137.04,6544.18) v1@6145.57,6535.65 ; v1@6649.71,6912.71 cw(c6641.17,6904.17) 6653.24,6904.17 cw(c6665.32,6904.17) v1@6656.78,6912.71 ; U4.24@6651.19,6869.52 ccw(c6646.23,6874.48) 6653.24,6874.48 ccw(c6660.26,6874.48) U4.24@6655.3,6869.52 ; U4.24@6653.24,6834 v1(6653.24,6916.24) ; v1(6664,7433) R36.6@7555.84,7433 ; v1@6667.54,7429.46 cw(c6676.07,7420.93) 6676.07,7433 cw(c6676.07,7445.07) v1@6667.54,7436.54 ; v1@7095.46,7429.46 ccw(c7086.93,7420.93) 7086.93,7433 ccw(c7086.93,7445.07) v1@7095.46,7436.54 ; v1@7102.54,7429.46 cw(c7111.07,7420.93) 7111.07,7433 cw(c7111.07,7445.07) v1@7102.54,7436.54 ; R36.6@7543.1,7428.76 ccw(c7532.86,7418.51) 7532.86,7433 ccw(c7532.86,7447.49) R36.6@7543.1,7437.24
  BottomLayer w6: v1(6149.11,6532.11) 6271,6654 6271,6874 6355,6958 6355,7124 v1(6664,7433) ; v1@6149.11,6537.11 ccw(c6149.11,6549.18) 6157.65,6540.65 ccw(c6166.18,6532.11) v1@6154.11,6532.11 ; v1@6649.71,6919.78 ccw(c6641.17,6928.32) 6653.24,6928.32 ccw(c6665.32,6928.32) v1@6656.78,6919.78 ; v1(6653.24,6916.24) 6653.24,6987.24 v1(7099,7433) ; v1@6659,7433 cw(c6646.93,7433) 6655.46,7424.46 cw(c6664,7415.93) v1@6664,7428 ; v1@7094,7433 cw(c7081.93,7433) 7090.46,7424.46 cw(c7099,7415.93) v1@7099,7428
EA14: R36.5 U2.6 U4.21 | length 3279.8
  TopLayer w6: U2.6@5966,6512.43 v1(6176.43,6512.43) ; U2.6@6001.52,6510.37 cw(c6006.48,6505.41) 6006.48,6512.43 cw(c6006.48,6519.44) U2.6@6001.52,6514.48 ; v1@6172.89,6508.89 ccw(c6164.35,6500.35) 6164.35,6512.43 ccw(c6164.35,6524.5) v1@6172.89,6515.96 ; v1@6708.76,6886.76 cw(c6700.23,6878.23) 6712.3,6878.23 cw(c6724.37,6878.23) v1@6715.84,6886.76 ; U4.21@6710.25,6869.52 ccw(c6705.29,6874.48) 6712.3,6874.48 ccw(c6719.31,6874.48) U4.21@6714.35,6869.52 ; U4.21@6712.3,6834 v1(6712.3,6890.3) ; v1(6732,7469) R36.5@7555.84,7469 ; v1@6735.54,7465.46 cw(c6744.07,7456.93) 6744.07,7469 cw(c6744.07,7481.07) v1@6735.54,7472.54 ; v1@7210.46,7465.46 ccw(c7201.93,7456.93) 7201.93,7469 ccw(c7201.93,7481.07) v1@7210.46,7472.54 ; v1@7217.54,7465.46 cw(c7226.07,7456.93) 7226.07,7469 cw(c7226.07,7481.07) v1@7217.54,7472.54 ; R36.5@7543.1,7464.76 ccw(c7532.86,7454.51) 7532.86,7469 ccw(c7532.86,7483.49) R36.5@7543.1,7473.24
  BottomLayer w6: v1(6176.43,6512.43) 6291,6627 6291,6866 6371,6946 6371,7110 6415,7154 ; v1@6176.43,6517.43 ccw(c6176.43,6529.5) 6184.96,6520.96 ccw(c6193.5,6512.43) v1@6181.43,6512.43 ; 6415.33,7153.66 v1(6732,7469) ; v1@6708.76,6893.84 ccw(c6700.23,6902.37) 6712.3,6902.37 ccw(c6724.37,6902.37) v1@6715.84,6893.84 ; v1(6712.3,6890.3) 6712.3,6967.3 v1(7214,7469) ; v1@6727,7469.01 cw(c6714.93,7469.04) 6723.45,7460.48 cw(c6731.96,7451.93) v1@6731.99,7464 ; v1@7209,7469 cw(c7196.93,7469) 7205.46,7460.46 cw(c7214,7451.93) v1@7214,7464
EA15: R37.8 U2.5 U4.22 | length 3415.4
  TopLayer w6: U2.5@5966,6492.74 v1(6201.74,6492.74) ; U2.5@6001.52,6490.69 cw(c6006.48,6485.73) 6006.48,6492.74 cw(c6006.48,6499.75) U2.5@6001.52,6494.79 ; v1@6198.2,6489.2 ccw(c6189.67,6480.67) 6189.67,6492.74 ccw(c6189.67,6504.81) v1@6198.2,6496.28 ; v1@6689.08,6909.08 cw(c6680.54,6900.54) 6692.61,6900.54 cw(c6704.69,6900.54) v1@6696.15,6909.08 ; U4.22@6690.56,6869.52 ccw(c6685.6,6874.48) 6692.61,6874.48 ccw(c6699.63,6874.48) U4.22@6694.67,6869.52 ; U4.22@6692.61,6834 v1(6692.61,6912.61) ; v1(6838,7534) R37.8@7555.84,7534 ; v1@6841.54,7530.46 cw(c6850.07,7521.93) 6850.07,7534 cw(c6850.07,7546.07) v1@6841.54,7537.54 ; v1@7248.46,7530.46 ccw(c7239.93,7521.93) 7239.93,7534 ccw(c7239.93,7546.07) v1@7248.46,7537.54 ; v1@7255.54,7530.46 cw(c7264.07,7521.93) 7264.07,7534 cw(c7264.07,7546.07) v1@7255.54,7537.54 ; R37.8@7543.1,7529.76 ccw(c7532.86,7519.51) 7532.86,7534 ccw(c7532.86,7548.49) R37.8@7543.1,7538.24
  BottomLayer w6: v1(6201.74,6492.74) 6310,6601 6310,6734 6345,6769 6345,6889 6392,6936 6392,7109 6542.23,7259.23 6562.23,7259.23 v1@6836,7533 ; v1@6201.74,6497.74 ccw(c6201.74,6509.81) 6210.28,6501.28 ccw(c6218.81,6492.74) v1@6206.74,6492.74 ; v1@6689.08,6916.15 ccw(c6680.54,6924.69) 6692.61,6924.69 ccw(c6704.69,6924.69) v1@6696.15,6916.15 ; v1(6692.61,6912.61) 6692.61,6974.61 v1(7252,7534) ; 6827.76,7524.76 cw(c6838,7514.51) v1@6838,7529 ; 6830.17,7527.17 ccw(c6823.34,7534) v1@6833,7534 ; v1@7247,7534 cw(c7234.93,7534) 7243.46,7525.46 cw(c7252,7516.93) v1@7252,7529
EA16: R37.7 U2.4 U4.23 | length 3856.1
  TopLayer w6: v1(5848,6474) U2.4@5966,6473.06 ; v1@5851.51,6470.44 cw(c5859.97,6461.83) 5860.07,6473.9 cw(c5860.17,6485.97) v1@5851.56,6477.51 ; 5924.88,6473.38 cw(c5924.81,6465.46) U2.4@5930.46,6471.02 ; 5926.17,6473.37 ccw(c5926.22,6479.47) U2.4@5930.5,6475.13 ; v1@6669.39,6889.39 cw(c6660.86,6880.86) 6672.93,6880.86 cw(c6685,6880.86) v1@6676.47,6889.39 ; U4.23@6670.88,6869.52 ccw(c6665.92,6874.48) 6672.93,6874.48 ccw(c6679.94,6874.48) U4.23@6674.98,6869.52 ; U4.23@6672.93,6834 v1(6672.93,6892.93) ; v1@7136,7645 cw(c7136,7632.93) 7144.54,7641.46 cw(c7153.07,7650) v1@7141,7650 ; v1(7136,7650) 7216,7570 R37.7@7555.84,7570 ; v1@7258.46,7566.46 ccw(c7249.93,7557.93) 7249.93,7570 ccw(c7249.93,7582.07) v1@7258.46,7573.54 ; v1@7265.54,7566.46 cw(c7274.07,7557.93) 7274.07,7570 cw(c7274.07,7582.07) v1@7265.54,7573.54 ; R37.7@7543.1,7565.76 ccw(c7532.86,7555.51) 7532.86,7570 ccw(c7532.86,7584.49) R37.7@7543.1,7574.24
  BottomLayer w6: v1@5844.46,6477.54 ccw(c5835.93,6486.07) 5848,6486.07 ccw(c5860.07,6486.07) v1@5851.54,6477.54 ; v1(5848,6474) 5848,6867 6152,7171 6152,7315 6487,7650 v1(7136,7650) ; v1@6669.39,6896.47 ccw(c6660.86,6905) 6672.93,6905 ccw(c6685,6905) v1@6676.47,6896.47 ; v1(6672.93,6892.93) 6672.93,6980.93 v1(7262,7570) ; v1@7132.46,7646.46 ccw(c7123.93,7637.93) 7123.93,7650 ccw(c7123.93,7662.07) v1@7132.46,7653.54 ; v1@7257,7570 cw(c7244.93,7570) 7253.46,7561.46 cw(c7262,7552.93) v1@7262,7565
EA17: R74.5 U2.3 | length 2519.3
  TopLayer w6: U2.3@5966,6453.37 v1(6043.96,6453.37) ; U2.3@6001.52,6451.32 cw(c6006.48,6446.36) 6006.48,6453.37 cw(c6006.48,6460.38) U2.3@6001.52,6455.42 ; v1@6040.42,6449.83 ccw(c6031.89,6441.3) 6031.89,6453.37 ccw(c6031.89,6465.44) v1@6040.42,6456.91
  BottomLayer w6: v1@6040.42,6456.91 ccw(c6031.89,6465.44) 6043.96,6465.44 ccw(c6056.03,6465.44) v1@6047.5,6456.91 ; v1(6043.96,6453.37) 6043.96,6886 6216.46,7058.5 6216.46,7269.46 6505,7558 7208,7558 7240,7590 7409,7590 7433,7566 R74.5@7555.84,7566 ; R74.5@7543.1,7561.76 ccw(c7532.86,7551.51) 7532.86,7566 ccw(c7532.86,7580.49) R74.5@7543.1,7570.24
EA18: R74.8 U2.2 | length 2686.7
  TopLayer w6: v1(5902.31,6433.69) U2.2@5966,6433.69 ; v1@5905.85,6430.15 cw(c5914.39,6421.61) 5914.39,6433.69 cw(c5914.39,6445.76) v1@5905.85,6437.22 ; U2.2@5930.48,6431.63 ccw(c5925.52,6426.67) 5925.52,6433.69 ccw(c5925.52,6440.7) U2.2@5930.48,6435.74
  BottomLayer w6: v1@5897.32,6433.69 ccw(c5885.24,6433.69) 5893.78,6442.22 ccw(c5902.31,6450.76) v1@5902.31,6438.68 ; v1(5902.31,6433.69) 5867,6469 5867,6858 6169.54,7160.54 6169.54,7306.54 6486,7623 7152,7623 7203,7674 R74.8@7555.84,7674 ; R74.8@7543.1,7669.76 ccw(c7532.86,7659.51) 7532.86,7674 ccw(c7532.86,7688.49) R74.8@7543.1,7678.24
EA19: R20.2 R37.6 U2.1 | length 3111.4
  TopLayer w6: v1(5853,6414) 6052.54,6414 R20.2@6086.54,6380 ; v1@5856.54,6410.46 cw(c5865.07,6401.93) 5865.07,6414 cw(c5865.07,6426.07) v1@5856.54,6417.54 ; U2.1@5930.48,6411.95 ccw(c5925.52,6406.99) 5925.52,6414 ccw(c5925.52,6421.01) U2.1@5930.48,6416.05 ; U2.1@6001.52,6411.95 cw(c6006.48,6406.99) 6006.48,6414 cw(c6006.48,6421.01) U2.1@6001.52,6416.05 ; 6054.69,6411.84 cw(c6022.85,6380) R20.2@6067.88,6380 ; 6059.44,6407.09 ccw(c6084.57,6432.21) R20.2@6084.57,6396.69 ; 6064.93,6401.6 cw(c6043.33,6380) R20.2@6073.88,6380 ; R20.2@6069.69,6396.85 ccw(c6084.57,6411.73) R20.2@6084.57,6390.69 ; v1@7163,7666 cw(c7163,7653.93) 7171.54,7662.46 cw(c7180.07,7671) v1@7168,7671 ; v1(7163,7671) 7228,7606 R37.6@7555.84,7606 ; R37.6@7543.1,7601.76 ccw(c7532.86,7591.51) 7532.86,7606 ccw(c7532.86,7620.49) R37.6@7543.1,7610.24
  BottomLayer w6: v1@5848,6414 ccw(c5835.93,6414) 5844.46,6422.54 ccw(c5853,6431.07) v1@5853,6419 ; v1(5853,6414) 5829,6438 5829,6873 6134,7178 6134,7325 6480,7671 v1(7163,7671) ; v1@7159.46,7667.46 ccw(c7150.93,7658.93) 7150.93,7671 ccw(c7150.93,7683.07) v1@7159.46,7674.54
EA20: R19.1 R37.5 U2.48 | length 3816.2
  TopLayer w6: U2.48@5135.21,6411.95 ccw(c5130.25,6406.99) 5130.25,6414 ccw(c5130.25,6421.01) U2.48@5135.21,6416.05 ; U2.48@5206.24,6411.95 cw(c5211.2,6406.99) 5211.2,6414 cw(c5211.2,6421.01) U2.48@5206.24,6416.05 ; R19.1@5214.74,6351.8 ccw(c5186.25,6380.28) 5226.54,6380.28 ccw(c5266.82,6380.28) R19.1@5238.33,6351.8 ; R19.1@5218.98,6347.56 ccw(c5200.74,6365.8) 5226.54,6365.8 ccw(c5252.33,6365.8) R19.1@5234.09,6347.56 ; v1@5225.46,6919.46 ccw(c5216.93,6910.93) 5216.93,6923 ccw(c5216.93,6935.07) v1@5225.46,6926.54 ; R19.1@5226.54,6340 5226.54,6405.46 5218,6414 5118,6414 5024,6508 5024,6827 5120,6923 v1(5229,6923) ; v1@7194,7689 cw(c7194,7676.93) 7202.54,7685.46 cw(c7211.07,7694) v1@7199,7694 ; v1(7194,7694) 7246,7642 R37.5@7555.84,7642 ; R37.5@7543.1,7637.76 ccw(c7532.86,7627.51) 7532.86,7642 ccw(c7532.86,7656.49) R37.5@7543.1,7646.24
  BottomLayer w6: v1(5229,6923) 5741,6923 6055,7237 6055,7322 6427,7694 v1(7194,7694) ; v1@5232.54,6919.46 cw(c5241.07,6910.93) 5241.07,6923 cw(c5241.07,6935.07) v1@5232.54,6926.54 ; v1@7190.46,7690.46 ccw(c7181.93,7681.93) 7181.93,7694 ccw(c7181.93,7706.07) v1@7190.46,7697.54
